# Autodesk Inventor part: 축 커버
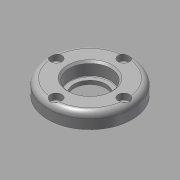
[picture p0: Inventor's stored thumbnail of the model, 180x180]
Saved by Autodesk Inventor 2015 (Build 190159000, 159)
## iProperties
Created: 2015-10
Part Number: 축 커버
Document SubType Name: Modeling
Designer: mdu
Density: 7.86 g/cm^3
Material: 강철, 연강
Mass: 76.1291 g
Surface Area: 48.0703 cm^2
Volume: 9.68563 cm^3
Appearance: 강철
Author: mdu
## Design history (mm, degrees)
sketch "스케치1"
  geometry: C1 r 22.355 at (0, 0) reference; C2 r 14 at (0, 0) reference; C3 r 1.23 at (0, 18) reference; 1 further point
extrude "돌출1" new body sketch "스케치1" distance "d0" = 8; taper "d1" = 0 deg
sketch "스케치2"
  geometry: C1 r 14 at (0, 0) reference; 1 further point
extrude "돌출2" join sketch "스케치2" distance "d2" = 3; taper "d3" = 0 deg
hole "구멍1" diameter "d6" = 17; stored, may be unused: countersink angle "d10" = 90 deg, drill point angle "d12" = 118 deg; dims "d4" = 10, "d5" = 10, "d7" = 6, "d8" = 23, "d9" = 2, "d11" = 8
hole "구멍2" diameter "d15" = 22; stored, may be unused: countersink angle "d19" = 90 deg, drill point angle "d21" = 0 deg; dims "d13" = 10, "d14" = 10, "d16" = 6, "d17" = 25, "d18" = 2, "d20" = 7
fillet "모깎기1" dims "d22" = 3, "d23" = 0.3
chamfer "모따기1" distance "d24" = 1; stored, may be unused: second distance "d25" = 2, angle "d26" = 45 deg
sketch "스케치3"
  geometry: 2 further points
hole "구멍3" sketch "스케치3" at (0, 18) diameter "d27" = 3.4; stored, may be unused: countersink angle "d31" = 90 deg, drill point angle "d33" = 118 deg; dims "d28" = 6, "d29" = 6, "d30" = 3.3, "d32" = 7
node "솔리드1"
pattern_circular "원형 패턴1" dims angle "d35" = 360 deg
node "참조1"
node "참조2"
node "참조3"
